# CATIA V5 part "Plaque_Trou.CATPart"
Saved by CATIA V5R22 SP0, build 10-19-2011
Part number: Plaque_Trou
Bounding box of the stored display mesh (mm): x -44 to 44, y -63.5 to 63.5, z 0 to 3
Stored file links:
  U:\S9A\PER\CAO\Assemblage\Cadre\Chariot_Y\Plaque_Trou.CATPart
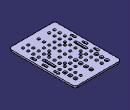
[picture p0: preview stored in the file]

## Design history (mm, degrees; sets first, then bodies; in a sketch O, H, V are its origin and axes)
Body1 (main body)
  Sketch1 on xy-plane, origin (0, 0, 0), H (1, 0, 0), V (0, 1, 0)
    point P1 (-44, 63.5)
    line L1 (-44, 63.5) -> (44, 63.5)
    line L2 (44, 63.5) -> (44, -63.5)
    line L3 (44, -63.5) -> (-44, -63.5)
    line L4 (-44, -63.5) -> (-44, 63.5)
    point P2 (44, 63.5)
    point P4 (-44, -63.5)
    length L1 = 88
    length L2 = 127
    horizontal: L1 H, L3 H
    vertical: L2 V, L4 V
    symmetry: P1 P2 V, P1 P4 H
  Pad1: profile Sketch1, direction (0, 0, 1), length 3
  Fillet1: radius 5, on edge [face of Pad1 from Sketch1.L4 | face of Pad1 from Sketch1.L1]; edge [face of Pad1 from Sketch1.L1 | face of Pad1 from Sketch1.L2]; edge [face of Pad1 from Sketch1.L2 | face of Pad1 from Sketch1.L3]; edge [face of Pad1 from Sketch1.L3 | face of Pad1 from Sketch1.L4]
  Sketch2 on end face of Pad1, origin (-7.5905, 33.6643, 3), H (1, 0, 0), V (0, 1, 0)
    point P1 (-22.4095, 16.3357)
    reference projected line E1 (51.5905, 29.8357) -> (-36.4095, 29.8357) from edge [face of Pad1 from Sketch1.L1 | end face of Pad1]
    reference projected line E2 (-36.4095, 29.8357) -> (-36.4095, -97.1643) from edge [face of Pad1 from Sketch1.L4 | end face of Pad1]
    distance P1 E1 = 13.5
    distance P1 E2 = 14
  Hole1: placed by Sketch2, at (-30, 50, 3) direction (0, 0, -1), diameter 7, through (limit type 6)
  RectPattern1: of Hole1, direction 1 instances 3, spacing 30, along end face of Pad1, direction 2 instances 3, spacing 10, along end face of Pad1 reversed
  Sketch3 on end face of Pad1, origin (-17.116, 25.8313, 3), H (1, 0, 0), V (0, 1, 0)
    point P1 (-2.884, 24.1687)
    reference projected line E1 (61.116, 37.6687) -> (-26.884, 37.6687) from edge [face of Pad1 from Sketch1.L1 | end face of Pad1]
    reference projected line E2 (-26.884, 37.6687) -> (-26.884, -89.3313) from edge [face of Pad1 from Sketch1.L4 | end face of Pad1]
    distance P1 E1 = 13.5
    distance P1 E2 = 24
  Hole2: placed by Sketch3, at (-20, 50, 3) direction (0, 0, -1), diameter 5, through (limit type 6)
  RectPattern2: of Hole2, direction 1 instances 2, spacing 40, along end face of Pad1, direction 2 instances 11, spacing 10, along end face of Pad1 reversed
  Sketch4 on end face of Pad1, origin (-30.3175, -51.5774, 3), H (1, 0, 0), V (0, 1, 0)
    point P1 (0.3175, 1.5774)
    reference projected line E1 (-13.6825, -11.9226) -> (74.3175, -11.9226) from edge [face of Pad1 from Sketch1.L3 | end face of Pad1]
    reference projected line E2 (-13.6825, 115.0774) -> (-13.6825, -11.9226) from edge [face of Pad1 from Sketch1.L4 | end face of Pad1]
    distance P1 E1 = 13.5
    distance P1 E2 = 14
  Hole3: placed by Sketch4, at (-30, -50, 3) direction (0, 0, -1), diameter 5, through (limit type 6)
  RectPattern3: of Hole3, direction 1 instances 3, spacing 30, along end face of Pad1, direction 2 instances 4, spacing 10, along end face of Pad1
  Sketch5 on end face of Pad1, origin (-9.996, -20.9478, 3), H (1, 0, 0), V (0, 1, 0)
    point P1 (-0.004, 0.9478)
    reference projected line E1 (-34.004, -42.5522) -> (53.996, -42.5522) from edge [face of Pad1 from Sketch1.L3 | end face of Pad1]
    reference projected line E2 (-34.004, 84.4478) -> (-34.004, -42.5522) from edge [face of Pad1 from Sketch1.L4 | end face of Pad1]
    distance P1 E1 = 43.5
    distance P1 E2 = 34
  Hole4: placed by Sketch5, at (-10, -20, 3) direction (0, 0, -1), diameter 5, through (limit type 6)
  RectPattern4: of Hole4, direction 1 instances 2, spacing 20, along end face of Pad1, direction 2 instances 2, spacing 10, along end face of Pad1 reversed
  Sketch6 on end face of Pad1, origin (0.4305, 21.7759, 3), H (1, 0, 0), V (0, 1, 0)
    point P1 (-0.4305, -1.7759)
    reference projected line E1 (43.5695, -85.2759) -> (43.5695, 41.7241) from edge [face of Pad1 from Sketch1.L2 | end face of Pad1]
    reference projected line E2 (43.5695, 41.7241) -> (-44.4305, 41.7241) from edge [face of Pad1 from Sketch1.L1 | end face of Pad1]
    distance P1 E1 = 44
    distance P1 E2 = 43.5
  Hole5: placed by Sketch6, at (0, 20, 3) direction (0, 0, -1), diameter 7, through (limit type 6)
  Sketch7 on end face of Pad1, origin (-30.3688, 19.8778, 3), H (1, 0, 0), V (0, 1, 0)
    point P1 (0.3688, 0.1222)
    reference projected line E1 (-13.6312, 43.6222) -> (-13.6312, -83.3778) from edge [face of Pad1 from Sketch1.L4 | end face of Pad1]
    reference projected line E2 (74.3688, 43.6222) -> (-13.6312, 43.6222) from edge [face of Pad1 from Sketch1.L1 | end face of Pad1]
    distance P1 E1 = 14
    distance P1 E2 = 43.5
  Hole6: placed by Sketch7, at (-30, 20, 3) direction (0, 0, -1), diameter 5, through (limit type 6)
  RectPattern5: of Hole6, direction 1 instances 2, spacing 20, along end face of Pad1
  Sketch8 on end face of Pad1, origin (29.6237, 20.058, 3), H (1, 0, 0), V (0, 1, 0)
    point P1 (0.3763, -0.058)
    reference projected line E1 (14.3763, -83.558) -> (14.3763, 43.442) from edge [face of Pad1 from Sketch1.L2 | end face of Pad1]
    reference projected line E2 (14.3763, 43.442) -> (-73.6237, 43.442) from edge [face of Pad1 from Sketch1.L1 | end face of Pad1]
    distance P1 E1 = 14
    distance P1 E2 = 43.5
  Hole7: placed by Sketch8, at (30, 20, 3) direction (0, 0, -1), diameter 5, through (limit type 6)
  RectPattern6: of Hole7, direction 1 instances 2, spacing 20, along end face of Pad1 reversed
  Sketch9 on end face of Pad1, origin (-11.0909, 29.6114, 3), H (1, 0, 0), V (0, 1, 0)
    point P1 (1.0909, 0.3886)
    reference projected line E1 (-32.9091, 33.8886) -> (-32.9091, -93.1114) from edge [face of Pad1 from Sketch1.L4 | end face of Pad1]
    reference projected line E2 (55.0909, 33.8886) -> (-32.9091, 33.8886) from edge [face of Pad1 from Sketch1.L1 | end face of Pad1]
    distance P1 E1 = 34
    distance P1 E2 = 33.5
  Hole8: placed by Sketch9, at (-10, 30, 3) direction (0, 0, -1), diameter 5, through (limit type 6)
  RectPattern7: of Hole8, direction 1 instances 2, spacing 20, along end face of Pad1
  Sketch10 on end face of Pad1, origin (-0.1658, 7.6036, 3), H (1, 0, 0), V (0, 1, 0)
    point P1 (0.1658, -7.6036)
    reference projected line E1 (44.1658, -71.1036) -> (44.1658, 55.8964) from edge [face of Pad1 from Sketch1.L2 | end face of Pad1]
    reference projected line E2 (44.1658, 55.8964) -> (-43.8342, 55.8964) from edge [face of Pad1 from Sketch1.L1 | end face of Pad1]
    distance P1 E1 = 44
    distance P1 E2 = 63.5
  Hole9: placed by Sketch10, at (0, 0, 3) direction (0, 0, -1), diameter 5, through (limit type 6)
  RectPattern8: of Hole9, direction 1 instances 3, spacing 10, along end face of Pad1, Nu 2
  RectPattern9: of Hole9, direction 1 instances 1, spacing 10, along end face of Pad1, direction 2 instances 3, spacing 10, along end face of Pad1, Nv 2
  Sketch11 on end face of Pad1, origin (-7.5335, -7.743, 3), H (1, 0, 0), V (0, 1, 0)
    point P1 (-7.4665, -7.257)
    reference projected line E1 (-36.4665, 71.243) -> (-36.4665, -55.757) from edge [face of Pad1 from Sketch1.L4 | end face of Pad1]
    reference projected line E2 (-36.4665, -55.757) -> (51.5335, -55.757) from edge [face of Pad1 from Sketch1.L3 | end face of Pad1]
    distance P1 E1 = 29
    distance P1 E2 = 48.5
  Hole10: placed by Sketch11, at (-15, -15, 3) direction (0, 0, -1), diameter 5, through (limit type 6)
  RectPattern10: of Hole10, direction 1 instances 2, spacing 30, along end face of Pad1, direction 2 instances 2, spacing 30, along end face of Pad1
  Sketch12 on end face of Pad1, origin (0, 0, 3), H (1, 0, 0), V (0, 1, 0)
    line L1 (32.5, 10) -> (32.5, -10)
    line L2 (27.5, -10) -> (27.5, 10)
    arc A1 centre (30, -10) radius 2.5 from (27.5, -10) to (32.5, -10) ccw
    arc A2 centre (30, 10) radius 2.5 from (27.5, 10) to (32.5, 10) cw
    point P6 (30, 10)
    reference projected line E1 (44, -63.5) -> (44, 63.5) from edge [face of Pad1 from Sketch1.L2 | end face of Pad1]
    radius A2 = 2.5
    radius A1 = 2.5
    distance L1 L2 = 5
    length L1 = 20
    distance L1 E1 = 11.5
    vertical: L1 V, L2 V
    fix: P6
  Pocket1: profile Sketch12, direction (0, 0, -1), length 3
  RectPattern11: of Pocket1, direction 1 instances 2, spacing 60, along end face of Pad1 reversed
  Sketch13 on end face of Pad1, origin (0, 0, 3), H (1, 0, 0), V (0, 1, 0)
    line L1 (-40, 5) -> (-36, 5)
    line L2 (-36, 5) -> (-36, -5)
    line L3 (-36, -5) -> (-40, -5)
    line L4 (-40, -5) -> (-40, 5)
    reference projected line E1 (44, 63.5) -> (-44, 63.5) from edge [face of Pad1 from Sketch1.L1 | end face of Pad1]
    reference projected line E2 (-44, 63.5) -> (-44, -63.5) from edge [face of Pad1 from Sketch1.L4 | end face of Pad1]
    length L2 = 10
    length L3 = 4
    distance L1 E1 = 58.5
    distance E2 L4 = 4
    horizontal: L1 H, L3 H
    vertical: L2 V, L4 V
  Pocket2: profile Sketch13, direction (0, 0, -1), through (limit type 3)
  RectPattern12: of Pocket2, direction 1 instances 2, spacing 76, along end face of Pad1, direction 2 instances 3, spacing 22, along end face of Pad1 reversed, Nv 2
  Fillet2: radius 2, on edge [face of Pocket2 from Sketch13.L4 | face of Pocket2 from Sketch13.L1]; edge [face of Pocket2 from Sketch13.L3 | face of Pocket2 from Sketch13.L4]; edge [face of Pocket2 from Sketch13.L2 | face of Pocket2 from Sketch13.L3]; edge [face of Pocket2 from Sketch13.L1 | face of Pocket2 from Sketch13.L2]; edge [face of RectPattern12 | face of RectPattern12] (x20)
